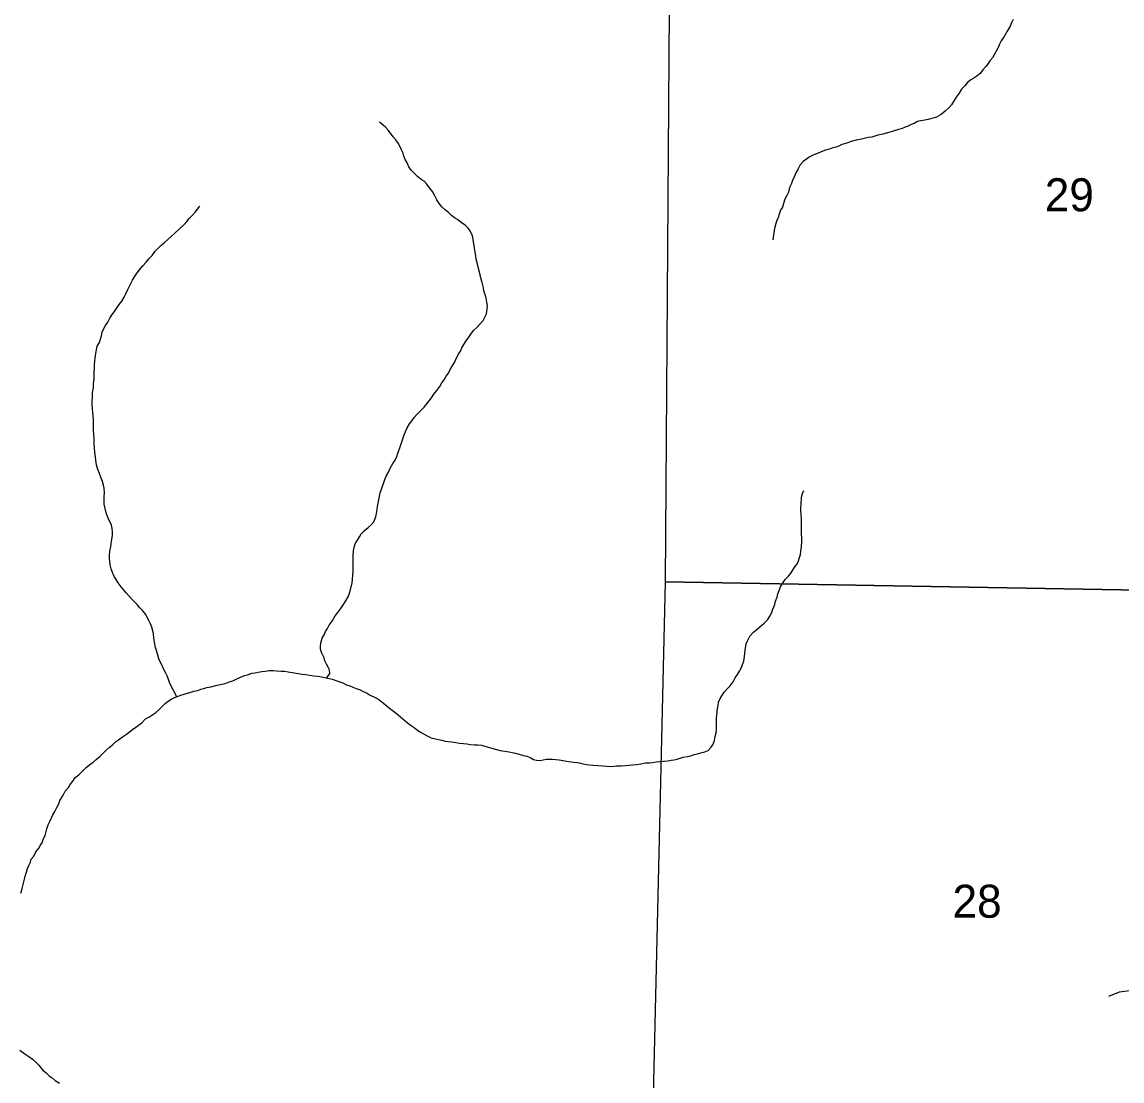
# Model space of a CAD drawing. Extents: x -10 to 158, y 8 to 33.
# Drawn here: x 41.577 to 42.973, y 19.269 to 20.612 of the extents above; entities that cross this region are included whole.
import ezdxf

# ---------------------------------------------------------------- set-up
doc = ezdxf.new("R2010")
doc.units = 0
for name, color, linetype in [('GM_X_Corporation', 7, 'Continuous'), ('GM_X_Minor_River', 7, 'Continuous'), ('GM_X_Section_Text', 7, 'Continuous')]:
    doc.layers.add(name, color=color, linetype=linetype)

msp = doc.modelspace()

# ---------------------------------------------------------------- linework, layer by layer
at = {"layer": 'GM_X_Corporation'}
for points in [[(43.4294, 20.9027), (43.4052, 19.8848), (42.3938, 19.9023), (42.4008, 20.9313)], [(42.3938, 19.9023), (43.4052, 19.8848), (43.3832, 18.8683), (42.3702, 18.8884)]]:
    msp.add_lwpolyline(points, close=True, dxfattribs=at)
at = {"layer": 'GM_X_Minor_River'}
for points in [[(42.8349, 20.6155), (42.8327, 20.6113), (42.8308, 20.6071), (42.8271, 20.6006), (42.8234, 20.5938), (42.8197, 20.5884), (42.8174, 20.5842), (42.8156, 20.5801)], [(42.8156, 20.5801), (42.8134, 20.5755), (42.8111, 20.5717), (42.8085, 20.5671), (42.8052, 20.5633), (42.8029, 20.5595), (42.8, 20.5557), (42.7962, 20.5518), (42.7929, 20.5469), (42.7887, 20.5438), (42.785, 20.5411), (42.7812, 20.5388), (42.7763, 20.535), (42.7734, 20.5312), (42.7692, 20.5273), (42.7663, 20.522), (42.7625, 20.517), (42.7566, 20.5071), (42.7532, 20.5033), (42.7487, 20.4991), (42.7435, 20.4949), (42.7375, 20.4918), (42.7329, 20.4902), (42.7269, 20.4886), (42.7227, 20.4878), (42.7178, 20.487), (42.7133, 20.4862), (42.7092, 20.4835), (42.7054, 20.4824), (42.7017, 20.4801), (42.6979, 20.4789), (42.6941, 20.4773), (42.6881, 20.4754), (42.6839, 20.4742), (42.6802, 20.473), (42.6696, 20.4699), (42.6632, 20.4687), (42.6553, 20.4663), (42.6507, 20.4659), (42.6425, 20.4636), (42.6357, 20.4624), (42.6292, 20.4608), (42.6236, 20.4588), (42.6176, 20.4569), (42.6138, 20.4549), (42.6097, 20.4538), (42.6059, 20.4526), (42.6017, 20.451), (42.5965, 20.4498), (42.5912, 20.4475), (42.5867, 20.4456), (42.5806, 20.4433), (42.5761, 20.4409), (42.5724, 20.4386), (42.5682, 20.4356), (42.5645, 20.4314), (42.5619, 20.426), (42.5589, 20.4211), (42.5571, 20.4157), (42.5549, 20.4116), (42.5534, 20.4074), (42.5512, 20.4024), (42.5497, 20.3967), (42.5475, 20.3925), (42.5453, 20.3876), (42.5434, 20.3823), (42.542, 20.3777), (42.5397, 20.3739), (42.5379, 20.3686), (42.5368, 20.3644), (42.535, 20.3606), (42.5335, 20.3568), (42.5324, 20.3522), (42.5317, 20.3485), (42.531, 20.3447), (42.5303, 20.3401), (42.5299, 20.3363)], [(42.1587, 20.2917), (42.1559, 20.3016), (42.1548, 20.3069), (42.1536, 20.3114), (42.1532, 20.3159), (42.1523, 20.3205), (42.1515, 20.3254), (42.1511, 20.3295), (42.1503, 20.3333), (42.1495, 20.3371), (42.1487, 20.3413), (42.1464, 20.3465), (42.1437, 20.3503), (42.1399, 20.3541), (42.1346, 20.3582), (42.13, 20.3619), (42.1262, 20.3641), (42.1224, 20.3671), (42.1182, 20.3709), (42.114, 20.3743), (42.1098, 20.378), (42.1067, 20.3821), (42.1037, 20.387), (42.101, 20.3919), (42.0979, 20.3972), (42.0941, 20.4021), (42.091, 20.4066), (42.0876, 20.4104), (42.0837, 20.4126), (42.0796, 20.416), (42.075, 20.4205), (42.0715, 20.4242), (42.0681, 20.4287), (42.0658, 20.4336), (42.0635, 20.4381), (42.0619, 20.4423), (42.0607, 20.4461), (42.0588, 20.4502), (42.0565, 20.4547), (42.0546, 20.4585), (42.0515, 20.463), (42.0484, 20.4668), (42.045, 20.4713), (42.0419, 20.475), (42.0385, 20.4788), (42.0308, 20.4855)], [(41.7227, 20.2931), (41.7261, 20.2977), (41.7306, 20.3031), (41.7347, 20.3076), (41.738, 20.3122), (41.7425, 20.3164), (41.7459, 20.3214), (41.7534, 20.329), (41.7575, 20.3325), (41.7624, 20.3367), (41.7665, 20.3405), (41.771, 20.3444), (41.783, 20.3555), (41.7863, 20.3593), (41.7893, 20.3631), (41.7931, 20.3669), (41.7968, 20.3711), (41.8028, 20.3788)], [(41.7739, 19.7568), (41.765, 19.7735), (41.763, 19.7784), (41.7615, 19.7833), (41.7595, 19.7875), (41.7568, 19.792), (41.7545, 19.7973), (41.7526, 19.8011), (41.751, 19.8048), (41.7498, 19.8094), (41.7479, 19.8154), (41.7467, 19.8192), (41.7455, 19.826), (41.7447, 19.8309), (41.7443, 19.8366), (41.7431, 19.8403), (41.7419, 19.8449), (41.7404, 19.849), (41.7384, 19.8536), (41.7361, 19.8573), (41.7346, 19.8611), (41.7308, 19.8656), (41.7269, 19.8694), (41.7235, 19.8735), (41.7201, 19.8772), (41.7162, 19.881), (41.7094, 19.8885), (41.7032, 19.896), (41.6994, 19.9013), (41.6967, 19.9054), (41.6944, 19.9092), (41.6921, 19.9141), (41.6905, 19.919), (41.6893, 19.9239), (41.6881, 19.9318), (41.6881, 19.936), (41.6888, 19.9417), (41.6899, 19.9466), (41.6906, 19.9512), (41.6913, 19.9561), (41.692, 19.9614), (41.6923, 19.966), (41.6919, 19.9701), (41.6907, 19.9743), (41.6865, 19.9833), (41.6842, 19.9898), (41.6826, 19.9954), (41.6814, 20.0011), (41.6814, 20.0053), (41.6817, 20.0109), (41.682, 20.0151), (41.6816, 20.0212), (41.6808, 20.0249), (41.6796, 20.0295), (41.6777, 20.034), (41.6757, 20.0397), (41.6734, 20.0449), (41.6718, 20.0506), (41.671, 20.0563), (41.6706, 20.0608), (41.6698, 20.0669), (41.6689, 20.0775), (41.6688, 20.0839), (41.6684, 20.09), (41.668, 20.0938), (41.6678, 20.1081), (41.667, 20.1172), (41.6666, 20.1221), (41.6665, 20.1263), (41.6665, 20.1305), (41.6668, 20.1373), (41.6667, 20.1426), (41.6678, 20.1483), (41.6682, 20.1536), (41.6688, 20.16), (41.6688, 20.1638), (41.6694, 20.1775), (41.6698, 20.1824), (41.6701, 20.1866), (41.6708, 20.1919), (41.6726, 20.2014), (41.6756, 20.2059), (41.677, 20.2101), (41.6781, 20.2143), (41.6792, 20.2189), (41.6807, 20.223), (41.6833, 20.2276), (41.6863, 20.2318), (41.6889, 20.2367), (41.6919, 20.2413), (41.6948, 20.2451), (41.6974, 20.249), (41.7004, 20.2539), (41.7038, 20.2585), (41.7068, 20.2634), (41.709, 20.2676), (41.7116, 20.2733), (41.7145, 20.279), (41.7175, 20.2851), (41.7201, 20.2893), (41.7227, 20.2931)], [(41.9637, 19.7804), (41.9679, 19.7861), (41.9674, 19.7907), (41.9659, 19.7944), (41.9636, 19.7982), (41.9617, 19.8024), (41.9605, 19.8061), (41.9578, 19.8118), (41.9562, 19.8171), (41.9558, 19.8216), (41.9569, 19.8265), (41.958, 19.8311), (41.9606, 19.8353), (41.9624, 19.8395), (41.965, 19.8433), (41.9669, 19.8475), (41.9706, 19.8524), (41.9747, 19.8593), (41.9781, 19.8635), (41.9818, 19.8685), (41.9844, 19.8726), (41.9881, 19.8784), (41.9911, 19.8833), (41.9929, 19.8879), (41.994, 19.8921), (41.9962, 19.9012), (41.9966, 19.905), (41.9972, 19.9118), (41.9976, 19.9156), (41.9974, 19.9364), (41.9977, 19.9409), (41.9984, 19.9447), (41.9999, 19.9504), (42.0029, 19.9554), (42.0055, 19.9596), (42.0077, 19.9634), (42.0118, 19.9676), (42.0163, 19.9714), (42.0204, 19.9745), (42.0238, 19.9787), (42.026, 19.9848), (42.0275, 19.9912), (42.0285, 19.9981), (42.0318, 20.0151), (42.0332, 20.0201), (42.0362, 20.0284), (42.0376, 20.0322), (42.0395, 20.0364), (42.0417, 20.0406), (42.0443, 20.0467), (42.0476, 20.0524), (42.0506, 20.0566), (42.0528, 20.0612), (42.0543, 20.0654), (42.0565, 20.0722), (42.0587, 20.0787), (42.0602, 20.0825), (42.0613, 20.0863), (42.0639, 20.0931), (42.0661, 20.0977), (42.0691, 20.1026), (42.0721, 20.1068), (42.075, 20.1106), (42.0784, 20.1145), (42.0836, 20.1202), (42.0874, 20.124), (42.0911, 20.1282), (42.0937, 20.132), (42.0967, 20.1358), (42.0997, 20.1404), (42.1034, 20.145), (42.1072, 20.15), (42.1101, 20.1549), (42.1127, 20.1587), (42.1153, 20.1633), (42.1183, 20.1671), (42.1209, 20.1724), (42.1239, 20.177), (42.1265, 20.1816), (42.1291, 20.1873), (42.131, 20.1911), (42.1336, 20.1949), (42.1354, 20.1991), (42.138, 20.2033), (42.1406, 20.2082), (42.144, 20.2128), (42.1477, 20.2178), (42.1507, 20.2216), (42.1544, 20.225), (42.1623, 20.2338), (42.1667, 20.2422), (42.1674, 20.2487), (42.1678, 20.2524), (42.167, 20.257), (42.1662, 20.2623), (42.165, 20.2664), (42.1634, 20.2713), (42.1626, 20.2751), (42.1611, 20.2819), (42.1595, 20.2876), (42.1587, 20.2917)], [(42.3736, 19.6731), (42.3773, 19.6735), (42.3819, 19.6743), (42.3913, 19.6752), (42.3966, 19.6756), (42.4008, 19.6764), (42.4049, 19.6768), (42.4087, 19.6776), (42.4162, 19.6799), (42.4215, 19.6808), (42.4257, 19.6819), (42.4302, 19.6835), (42.4343, 19.6843), (42.4385, 19.6855), (42.4434, 19.687), (42.4479, 19.6886), (42.4516, 19.6928), (42.4542, 19.6966), (42.4557, 19.7012), (42.4568, 19.7061), (42.4579, 19.711), (42.4582, 19.7148), (42.4585, 19.7209), (42.4585, 19.7292), (42.4588, 19.7338), (42.4595, 19.7417), (42.4606, 19.7455), (42.4609, 19.7497), (42.4631, 19.7543), (42.4661, 19.7592), (42.4687, 19.763), (42.4721, 19.7669), (42.4758, 19.7707), (42.4796, 19.7756), (42.4821, 19.7806), (42.4851, 19.7848), (42.4874, 19.789), (42.4896, 19.7928), (42.4914, 19.7977), (42.4929, 19.8019), (42.494, 19.8076), (42.4947, 19.8156), (42.4961, 19.8239), (42.4983, 19.8285), (42.5009, 19.8334), (42.5054, 19.8388), (42.5099, 19.8422), (42.5189, 19.8499), (42.5234, 19.8548), (42.526, 19.8587), (42.5282, 19.8625), (42.5297, 19.8678), (42.5323, 19.8735), (42.5334, 19.8781), (42.5352, 19.883), (42.5363, 19.8872), (42.5378, 19.8914), (42.5396, 19.8959), (42.5422, 19.9005), (42.5456, 19.9054), (42.5497, 19.9097), (42.553, 19.9139), (42.5571, 19.92), (42.5597, 19.9238), (42.562, 19.9276), (42.5638, 19.9333), (42.5649, 19.9371), (42.5656, 19.9412), (42.5663, 19.9466), (42.5666, 19.9538), (42.5666, 19.9583), (42.5662, 19.9628), (42.5661, 19.9681), (42.5664, 19.9727), (42.5664, 19.9769), (42.5664, 19.9814), (42.5659, 19.9882), (42.5655, 19.9924), (42.5654, 19.9962), (42.5658, 20.0003), (42.5664, 20.0098), (42.5675, 20.0144), (42.569, 20.0182)], [(41.85, 19.7793), (41.8545, 19.7816), (41.8594, 19.7835), (41.8632, 19.7843), (41.8688, 19.7867), (41.873, 19.7871), (41.8771, 19.7879), (41.8816, 19.7887), (41.8858, 19.7891), (41.8907, 19.7899), (41.8964, 19.79), (41.9002, 19.7896), (41.9062, 19.7893), (41.9104, 19.789), (41.9149, 19.7883), (41.9202, 19.7875), (41.9251, 19.7868), (41.9327, 19.7854), (41.9373, 19.7851), (41.9422, 19.784), (41.9475, 19.7833), (41.952, 19.7826), (41.9577, 19.7819), (41.9668, 19.7797), (41.9706, 19.779), (41.9778, 19.7764), (41.9842, 19.7742), (41.9888, 19.7719), (41.9934, 19.7705), (41.9972, 19.769), (42.0013, 19.7671), (42.0063, 19.7653), (42.0101, 19.7634), (42.0142, 19.7616), (42.018, 19.7593), (42.0264, 19.7553), (42.0302, 19.753), (42.0344, 19.75), (42.0382, 19.747), (42.0436, 19.7422), (42.0485, 19.7384), (42.0523, 19.7354), (42.0576, 19.7313), (42.0664, 19.7235), (42.071, 19.7201), (42.0748, 19.7175), (42.0794, 19.7141), (42.0836, 19.7115), (42.0912, 19.707), (42.0965, 19.7048), (42.1018, 19.7034), (42.1056, 19.7023), (42.1101, 19.7015), (42.1143, 19.7005), (42.1181, 19.7001), (42.1226, 19.6994), (42.1279, 19.6987), (42.1325, 19.698), (42.1374, 19.6976), (42.1416, 19.6969), (42.1465, 19.6962), (42.151, 19.6959), (42.1556, 19.6959), (42.1601, 19.6952), (42.1646, 19.6941), (42.1703, 19.6923), (42.1745, 19.6912), (42.1791, 19.6897), (42.184, 19.6886), (42.1953, 19.6869), (42.1991, 19.6858), (42.2033, 19.685), (42.2082, 19.684), (42.2135, 19.6821), (42.2177, 19.6814), (42.2219, 19.6795), (42.2264, 19.6773), (42.2302, 19.6762), (42.2348, 19.6759), (42.2423, 19.6775), (42.2461, 19.6775), (42.2503, 19.6776), (42.2586, 19.6769), (42.2662, 19.6754), (42.2711, 19.6747), (42.2771, 19.6736), (42.2821, 19.6733), (42.2874, 19.6722), (42.2931, 19.6708), (42.3014, 19.6701), (42.3078, 19.6694), (42.3139, 19.6691), (42.3192, 19.6688), (42.3256, 19.6684), (42.3316, 19.6689), (42.3373, 19.6689), (42.3426, 19.6694), (42.357, 19.6706), (42.3622, 19.6715), (42.3683, 19.6727), (42.3736, 19.6731)], [(41.5759, 19.5077), (41.5777, 19.5134), (41.5806, 19.5255), (41.5814, 19.5293), (41.5832, 19.5343), (41.5843, 19.5388), (41.5858, 19.5426), (41.588, 19.5468), (41.5891, 19.5506), (41.5921, 19.5544), (41.595, 19.5601), (41.5988, 19.5647), (41.6006, 19.5685), (41.6032, 19.5723), (41.6043, 19.5761), (41.6066, 19.5807), (41.6087, 19.5894), (41.6106, 19.5944), (41.6128, 19.5986), (41.6165, 19.6069), (41.6191, 19.6111), (41.6217, 19.6161), (41.6239, 19.621), (41.6254, 19.6252), (41.6291, 19.6309), (41.6321, 19.637), (41.6362, 19.6416), (41.6384, 19.6454), (41.6418, 19.6496), (41.6448, 19.6542), (41.6493, 19.6576), (41.6541, 19.6622), (41.6586, 19.6668), (41.6635, 19.6706), (41.6676, 19.6737), (41.6714, 19.6772), (41.6759, 19.681), (41.6804, 19.6852), (41.6841, 19.689), (41.6879, 19.6925), (41.6916, 19.6955), (41.6961, 19.6997), (41.6999, 19.7021), (41.7048, 19.7059), (41.71, 19.7094), (41.7138, 19.712), (41.7175, 19.7151), (41.7216, 19.7182), (41.7292, 19.7236), (41.734, 19.7285), (41.7382, 19.7308), (41.7434, 19.7343), (41.7472, 19.7366), (41.7513, 19.7404), (41.7588, 19.7481), (41.7629, 19.7512), (41.7674, 19.7539), (41.7719, 19.7562), (41.7787, 19.7585), (41.7874, 19.7612), (41.7915, 19.7624), (41.7953, 19.7636), (41.8002, 19.7648), (41.8043, 19.7663), (41.8081, 19.7671), (41.8119, 19.7683), (41.8168, 19.7691), (41.8232, 19.7711), (41.8289, 19.7723), (41.8349, 19.7735), (41.8394, 19.7754), (41.8447, 19.777), (41.85, 19.7793)], [(42.9931, 19.3849), (42.9693, 19.382), (42.9558, 19.3766)], [(41.5745, 19.3084), (41.581, 19.304), (41.5859, 19.3006), (41.5905, 19.2972), (41.5947, 19.2935), (41.5985, 19.2897), (41.6035, 19.2837), (41.6081, 19.28), (41.6119, 19.2759), (41.6157, 19.2736), (41.6195, 19.2699), (41.6248, 19.2669)]]:
    msp.add_lwpolyline(points, dxfattribs=at)

# ---------------------------------------------------------------- texts
at = {"layer": 'GM_X_Section_Text'}
for s, p in [('29', (42.8749, 20.3723)), ('28', (42.7579, 19.4765))]:
    msp.add_text(s, height=0.04186, rotation=0, dxfattribs=at).set_placement(p)

doc.saveas('drawing.dxf')
